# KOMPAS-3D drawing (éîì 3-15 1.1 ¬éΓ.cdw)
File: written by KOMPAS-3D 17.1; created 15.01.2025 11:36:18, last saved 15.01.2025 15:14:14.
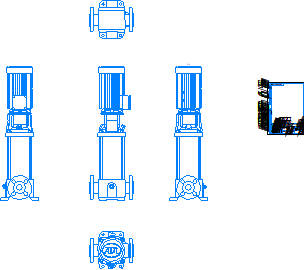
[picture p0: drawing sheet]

Sheet 1: A4, portrait

Title block, sheet 1: name: ВМН 3-15 1.1 кВт; designation: ВМН 3-15 1.1 кВт; material: Сталь 10  ГОСТ 1050-2013; mass: 68,16; sheets: 1; sheet format: A4; stored path: \\adlc.lan\data\АДЛ_ПКД\3D-модели\ADL production\Насосы ГРАНПАМП\Насосы ВМН\ВМН3\KOMPAS 3D\ВМН 3-15 1.1 кВт.cdw

Views: Проекционный вид 2, Проекционный вид 3, Проекционный вид 4, Проекционный вид 6
Referenced files in \\adlc.lan\data\АДЛ_ПКД\3D-модели\ADL production\Насосы ГРАНПАМП\Насосы ВМН\ВМН3\KOMPAS 3D\: ВМН 3-15 1.1 кВт.m3d
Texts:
  Andrey
  АДЛ
Dimensions and other numbers on the sheet: 1:1; 1; 68,16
